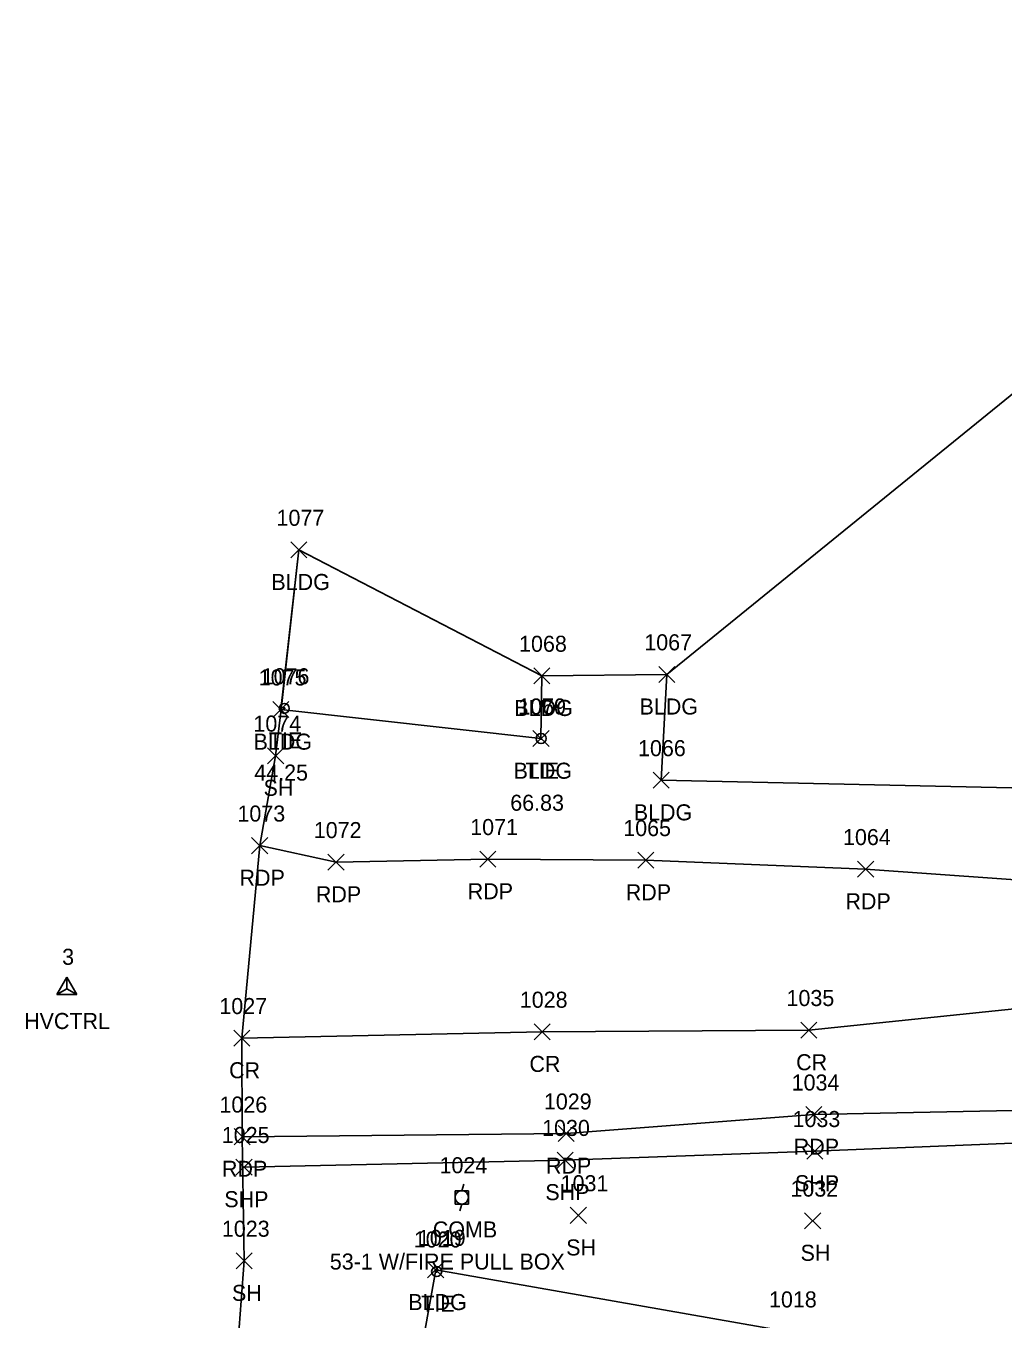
# Model space of a CAD drawing. Extents: x 1716490 to 1717645, y 888034 to 890004.
# Drawn here: x 1716642.2 to 1716763.9, y 888185.6 to 888346.8 of the extents above; entities that cross this region are included whole.
import ezdxf

# ---------------------------------------------------------------- set-up
doc = ezdxf.new("R2010")
doc.units = 0
for name, color, linetype in [('C_A', 7, 'Continuous'), ('C_C', 7, 'Continuous'), ('C_I', 7, 'Continuous'), ('CBP', 7, 'Continuous'), ('CPSM', 7, 'Continuous'), ('L_A', 7, 'Continuous'), ('L_I', 7, 'Continuous'), ('L_TIC', 7, 'Continuous'), ('LBC', 7, 'Continuous'), ('LSOGP', 7, 'Continuous'), ('P_A', 7, 'Continuous'), ('P_I', 7, 'Continuous'), ('P_TIC', 7, 'Continuous'), ('PET', 7, 'Continuous'), ('PRC', 7, 'Continuous'), ('PSP', 7, 'Continuous'), ('U_A', 7, 'Continuous'), ('U_C', 7, 'Continuous'), ('U_I', 7, 'Continuous'), ('UP', 7, 'Continuous')]:
    doc.layers.add(name, color=color, linetype=linetype)

msp = doc.modelspace()

# ---------------------------------------------------------------- linework, layer by layer
at = {"layer": 'CBP'}
for centre, radius in [((1716674.39, 888261.7), 0.625), ((1716674.39, 888261.7), 0.0833), ((1716706.38, 888257.94), 0.625), ((1716706.38, 888257.94), 0.0833), ((1716693.37, 888191.51), 0.625), ((1716693.37, 888191.51), 0.0833)]:
    msp.add_circle(centre, radius, dxfattribs=at)
at = {"layer": 'CPSM'}
for p, q in [((1716646.03, 888226.02), (1716647.28, 888228.18)), ((1716646.03, 888226.02), (1716647.28, 888228.18)), ((1716646.03, 888226.02), (1716647.28, 888228.18)), ((1716646.03, 888226.02), (1716647.28, 888228.18)), ((1716646.03, 888226.02), (1716647.28, 888228.18)), ((1716646.03, 888226.02), (1716647.28, 888228.18)), ((1716646.03, 888226.02), (1716647.28, 888228.18)), ((1716646.03, 888226.02), (1716647.28, 888228.18)), ((1716646.03, 888226.02), (1716647.28, 888228.18)), ((1716648.53, 888226.02), (1716647.28, 888228.18)), ((1716647.28, 888226.74), (1716647.28, 888228.18)), ((1716648.53, 888226.02), (1716647.28, 888228.18)), ((1716647.28, 888226.74), (1716647.28, 888228.18)), ((1716648.53, 888226.02), (1716647.28, 888228.18)), ((1716647.28, 888226.74), (1716647.28, 888228.18)), ((1716648.53, 888226.02), (1716647.28, 888228.18)), ((1716647.28, 888226.74), (1716647.28, 888228.18)), ((1716648.53, 888226.02), (1716647.28, 888228.18)), ((1716647.28, 888226.74), (1716647.28, 888228.18)), ((1716648.53, 888226.02), (1716647.28, 888228.18)), ((1716647.28, 888226.74), (1716647.28, 888228.18)), ((1716648.53, 888226.02), (1716647.28, 888228.18)), ((1716647.28, 888226.74), (1716647.28, 888228.18)), ((1716648.53, 888226.02), (1716647.28, 888228.18)), ((1716647.28, 888226.74), (1716647.28, 888228.18)), ((1716648.53, 888226.02), (1716647.28, 888228.18)), ((1716647.28, 888226.74), (1716647.28, 888228.18)), ((1716646.03, 888226.02), (1716647.28, 888226.74)), ((1716646.03, 888226.02), (1716647.28, 888226.74)), ((1716646.03, 888226.02), (1716647.28, 888226.74)), ((1716646.03, 888226.02), (1716647.28, 888226.74)), ((1716646.03, 888226.02), (1716647.28, 888226.74)), ((1716646.03, 888226.02), (1716647.28, 888226.74)), ((1716646.03, 888226.02), (1716647.28, 888226.74)), ((1716646.03, 888226.02), (1716647.28, 888226.74)), ((1716646.03, 888226.02), (1716647.28, 888226.74)), ((1716647.28, 888226.74), (1716647.28, 888226.74)), ((1716647.28, 888226.74), (1716648.53, 888226.02)), ((1716647.28, 888226.74), (1716647.28, 888226.74)), ((1716647.28, 888226.74), (1716648.53, 888226.02)), ((1716647.28, 888226.74), (1716647.28, 888226.74)), ((1716647.28, 888226.74), (1716648.53, 888226.02)), ((1716647.28, 888226.74), (1716647.28, 888226.74)), ((1716647.28, 888226.74), (1716648.53, 888226.02)), ((1716647.28, 888226.74), (1716647.28, 888226.74)), ((1716647.28, 888226.74), (1716648.53, 888226.02)), ((1716647.28, 888226.74), (1716647.28, 888226.74)), ((1716647.28, 888226.74), (1716648.53, 888226.02)), ((1716647.28, 888226.74), (1716647.28, 888226.74)), ((1716647.28, 888226.74), (1716648.53, 888226.02)), ((1716647.28, 888226.74), (1716647.28, 888226.74)), ((1716647.28, 888226.74), (1716648.53, 888226.02)), ((1716647.28, 888226.74), (1716647.28, 888226.74)), ((1716647.28, 888226.74), (1716648.53, 888226.02)), ((1716646.03, 888226.02), (1716648.53, 888226.02)), ((1716646.03, 888226.02), (1716648.53, 888226.02)), ((1716646.03, 888226.02), (1716648.53, 888226.02)), ((1716646.03, 888226.02), (1716648.53, 888226.02)), ((1716646.03, 888226.02), (1716648.53, 888226.02)), ((1716646.03, 888226.02), (1716648.53, 888226.02)), ((1716646.03, 888226.02), (1716648.53, 888226.02)), ((1716646.03, 888226.02), (1716648.53, 888226.02)), ((1716646.03, 888226.02), (1716648.53, 888226.02))]:
    msp.add_line(p, q, dxfattribs=at)
at = {"layer": 'L_TIC'}
for points in [[(1716675.19, 888280.45), (1716677.19, 888282.45)], [(1716677.19, 888280.45), (1716675.19, 888282.45)], [(1716721.06, 888264.93), (1716723.06, 888266.93)], [(1716723.06, 888264.93), (1716721.06, 888266.93)], [(1716705.46, 888264.75), (1716707.46, 888266.75)], [(1716707.46, 888264.75), (1716705.46, 888266.75)], [(1716672.97, 888260.55), (1716674.97, 888262.55)], [(1716674.97, 888260.55), (1716672.97, 888262.55)], [(1716705.37, 888256.93), (1716707.37, 888258.93)], [(1716707.37, 888256.93), (1716705.37, 888258.93)], [(1716672.31, 888254.8), (1716674.31, 888256.8)], [(1716674.31, 888254.8), (1716672.31, 888256.8)], [(1716720.34, 888251.74), (1716722.34, 888253.74)], [(1716722.34, 888251.74), (1716720.34, 888253.74)], [(1716710.02, 888197.52), (1716712.02, 888199.52)], [(1716712.02, 888197.52), (1716710.02, 888199.52)], [(1716739.22, 888196.85), (1716741.22, 888198.85)], [(1716741.22, 888196.85), (1716739.22, 888198.85)], [(1716668.38, 888191.85), (1716670.38, 888193.85)], [(1716670.38, 888191.85), (1716668.38, 888193.85)], [(1716692.25, 888190.71), (1716694.25, 888192.71)], [(1716694.25, 888190.71), (1716692.25, 888192.71)]]:
    msp.add_lwpolyline(points, dxfattribs=at)
at = {"layer": 'LBC'}
for points in [[(1716790.15, 888346.76), (1716790.15, 888340.32), (1716789.91, 888340.16), (1716789.24, 888334.17), (1716788.4, 888319.78), (1716786.54, 888291.65), (1716784, 888251.37), (1716721.34, 888252.74), (1716722.06, 888265.93)], [(1716706.46, 888265.75), (1716706.37, 888257.93), (1716673.97, 888261.55), (1716676.19, 888281.45)], [(1716763.17, 888137.56), (1716770.27, 888178.02), (1716736.98, 888184.04), (1716693.25, 888191.71), (1716689.55, 888170.9)]]:
    msp.add_lwpolyline(points, dxfattribs=at)
at = {"layer": 'LSOGP'}
msp.add_lwpolyline([(1716927.78, 888315.88), (1716905.33, 888322.14), (1716871.24, 888333.89), (1716808.97, 888341.31), (1716791.42, 888346.37), (1716790.32, 888340.43), (1716790.15, 888340.32), (1716789.9, 888340.16), (1716789.24, 888334.17), (1716791.29, 888331.62), (1716789.78, 888320.76), (1716788.41, 888319.78), (1716722.06, 888265.93), (1716706.46, 888265.74), (1716676.19, 888281.45), (1716673.98, 888261.56), (1716673.31, 888255.8), (1716671.32, 888244.59), (1716669.08, 888220.6), (1716669.13, 888208.32), (1716669.38, 888192.85), (1716667.9, 888172.89)], dxfattribs=at)
at = {"layer": 'P_TIC'}
for points in [[(1716670.32, 888243.59), (1716672.32, 888245.59)], [(1716672.32, 888243.59), (1716670.32, 888245.59)], [(1716679.83, 888241.53), (1716681.83, 888243.53)], [(1716681.83, 888241.53), (1716679.83, 888243.53)], [(1716698.75, 888241.91), (1716700.75, 888243.91)], [(1716700.75, 888241.91), (1716698.75, 888243.91)], [(1716718.44, 888241.78), (1716720.44, 888243.78)], [(1716720.44, 888241.78), (1716718.44, 888243.78)], [(1716745.82, 888240.66), (1716747.82, 888242.66)], [(1716747.82, 888240.66), (1716745.82, 888242.66)], [(1716705.5, 888220.39), (1716707.5, 888222.39)], [(1716707.5, 888220.39), (1716705.5, 888222.39)], [(1716738.73, 888220.6), (1716740.73, 888222.6)], [(1716740.73, 888220.6), (1716738.73, 888222.6)], [(1716668.08, 888219.6), (1716670.08, 888221.6)], [(1716670.08, 888219.6), (1716668.08, 888221.6)], [(1716739.37, 888210.07), (1716741.37, 888212.07)], [(1716741.37, 888210.07), (1716739.37, 888212.07)], [(1716668.13, 888207.32), (1716670.13, 888209.32)], [(1716670.13, 888207.32), (1716668.13, 888209.32)], [(1716708.51, 888207.71), (1716710.51, 888209.71)], [(1716710.51, 888207.71), (1716708.51, 888209.71)], [(1716739.48, 888205.52), (1716741.48, 888207.52)], [(1716741.48, 888205.52), (1716739.48, 888207.52)], [(1716668.37, 888203.53), (1716670.37, 888205.53)], [(1716670.37, 888203.53), (1716668.37, 888205.53)], [(1716708.37, 888204.41), (1716710.37, 888206.41)], [(1716710.37, 888204.41), (1716708.37, 888206.41)]]:
    msp.add_lwpolyline(points, dxfattribs=at)
at = {"layer": 'PET'}
msp.add_lwpolyline([(1716669.13, 888208.32), (1716709.51, 888208.71), (1716740.37, 888211.07), (1716775.56, 888211.78), (1716802.02, 888213.01), (1716840.45, 888216.11), (1716878.66, 888218.97), (1716877.6, 888230.5), (1716876.88, 888242.85), (1716857.91, 888241.59), (1716836.63, 888239.83), (1716814.63, 888240.15), (1716785.06, 888241.32), (1716771.93, 888239.87), (1716746.82, 888241.66), (1716719.44, 888242.78), (1716699.75, 888242.91), (1716680.83, 888242.53), (1716671.32, 888244.59)], dxfattribs=at)
at = {"layer": 'PRC'}
msp.add_lwpolyline([(1716669.08, 888220.6), (1716706.5, 888221.39), (1716739.73, 888221.6), (1716772.98, 888225.05), (1716801.23, 888226.28), (1716838.45, 888228.36), (1716877.6, 888230.5)], dxfattribs=at)
at = {"layer": 'PSP'}
msp.add_lwpolyline([(1716669.37, 888204.53), (1716709.37, 888205.41), (1716740.48, 888206.52), (1716776.45, 888207.97), (1716801.78, 888208.86), (1716839.96, 888211.48)], dxfattribs=at)
at = {"layer": 'UP'}
for p, q in [((1716696.75, 888202.42), (1716696.5, 888201.59)), ((1716695.67, 888199.92), (1716695.67, 888201.59)), ((1716695.67, 888201.59), (1716697.34, 888201.59)), ((1716696.5, 888200.76), (1716696.5, 888200.76)), ((1716697.34, 888201.59), (1716697.34, 888199.92)), ((1716697.34, 888199.92), (1716695.67, 888199.92)), ((1716696.25, 888199.09), (1716696.5, 888199.92))]:
    msp.add_line(p, q, dxfattribs=at)
msp.add_circle((1716696.5, 888200.76), 0.833, dxfattribs=at)

# ---------------------------------------------------------------- texts
at = {"layer": 'C_A'}
for s, p in [('TIE', (1716672.47, 888256.7)), ('TIE', (1716704.46, 888252.94)), ('HVCTRL', (1716641.97, 888221.74)), ('HVCTRL', (1716641.97, 888221.74)), ('HVCTRL', (1716641.97, 888221.74)), ('HVCTRL', (1716641.97, 888221.74)), ('HVCTRL', (1716641.97, 888221.74)), ('HVCTRL', (1716641.97, 888221.74)), ('HVCTRL', (1716641.97, 888221.74)), ('HVCTRL', (1716641.97, 888221.74)), ('HVCTRL', (1716641.97, 888221.74)), ('TIE', (1716691.45, 888186.51))]:
    msp.add_text(s, height=2, dxfattribs=at).set_placement(p)
at = {"layer": 'C_C'}
for s, p in [('44.25', (1716670.65, 888252.7)), ('66.83', (1716702.54, 888248.94))]:
    msp.add_text(s, height=2, dxfattribs=at).set_placement(p)
at = {"layer": 'C_I'}
for s, p in [('1076', (1716671.57, 888264.7)), ('1070', (1716703.52, 888260.94)), ('3', (1716646.71, 888229.74)), ('3', (1716646.71, 888229.74)), ('3', (1716646.71, 888229.74)), ('3', (1716646.71, 888229.74)), ('3', (1716646.71, 888229.74)), ('3', (1716646.71, 888229.74)), ('3', (1716646.71, 888229.74)), ('3', (1716646.71, 888229.74)), ('3', (1716646.71, 888229.74)), ('1020', (1716690.52, 888194.51))]:
    msp.add_text(s, height=2, dxfattribs=at).set_placement(p)
at = {"layer": 'L_A'}
for s, p in [('BLDG', (1716672.78, 888276.45)), ('BLDG', (1716703.05, 888260.75)), ('BLDG', (1716718.65, 888260.93)), ('BLDG', (1716670.56, 888256.55)), ('BLDG', (1716702.96, 888252.93)), ('SH', (1716671.8, 888250.8)), ('BLDG', (1716717.93, 888247.74)), ('SH', (1716709.51, 888193.52)), ('SH', (1716738.71, 888192.85)), ('SH', (1716667.87, 888187.85)), ('BLDG', (1716689.84, 888186.71))]:
    msp.add_text(s, height=2, dxfattribs=at).set_placement(p)
at = {"layer": 'L_I'}
for s, p in [('1077', (1716673.42, 888284.45)), ('1068', (1716703.64, 888268.75)), ('1067', (1716719.24, 888268.93)), ('1075', (1716671.2, 888264.55)), ('1069', (1716703.55, 888260.93)), ('1074', (1716670.54, 888258.8)), ('1066', (1716718.46, 888255.74)), ('1031', (1716708.82, 888201.52)), ('1032', (1716737.45, 888200.85)), ('1023', (1716666.61, 888195.85)), ('1019', (1716691.03, 888194.71)), ('1018', (1716734.78, 888187.04))]:
    msp.add_text(s, height=2, dxfattribs=at).set_placement(p)
at = {"layer": 'P_A'}
for s, p in [('RDP', (1716668.81, 888239.59)), ('RDP', (1716678.32, 888237.53)), ('RDP', (1716697.24, 888237.91)), ('RDP', (1716716.93, 888237.78)), ('RDP', (1716744.3, 888236.66)), ('CR', (1716704.93, 888216.39)), ('CR', (1716738.16, 888216.6)), ('CR', (1716667.51, 888215.6)), ('RDP', (1716737.86, 888206.07)), ('RDP', (1716706.99, 888203.71)), ('RDP', (1716666.62, 888203.32)), ('SHP', (1716706.91, 888200.41)), ('SHP', (1716738.01, 888201.52)), ('SHP', (1716666.91, 888199.53))]:
    msp.add_text(s, height=2, dxfattribs=at).set_placement(p)
at = {"layer": 'P_I'}
for s, p in [('1073', (1716668.55, 888247.59)), ('1072', (1716678.06, 888245.53)), ('1071', (1716697.55, 888245.91)), ('1065', (1716716.62, 888245.78)), ('1064', (1716744, 888244.66)), ('1035', (1716736.96, 888224.6)), ('1027', (1716666.3, 888223.6)), ('1028', (1716703.73, 888224.39)), ('1034', (1716737.6, 888214.07)), ('1029', (1716706.73, 888211.71)), ('1026', (1716666.31, 888211.32)), ('1030', (1716706.51, 888208.41)), ('1033', (1716737.71, 888209.52)), ('1025', (1716666.6, 888207.53))]:
    msp.add_text(s, height=2, dxfattribs=at).set_placement(p)
at = {"layer": 'U_A'}
msp.add_text('COMB', height=2, dxfattribs=at).set_placement((1716692.89, 888195.76))
at = {"layer": 'U_C'}
msp.add_text('53-1 W/FIRE PULL BOX', height=2, dxfattribs=at).set_placement((1716680.06, 888191.76))
at = {"layer": 'U_I'}
msp.add_text('1024', height=2, dxfattribs=at).set_placement((1716693.73, 888203.76))

doc.saveas('drawing.dxf')
